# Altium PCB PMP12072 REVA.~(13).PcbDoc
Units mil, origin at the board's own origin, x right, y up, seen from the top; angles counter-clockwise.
Board outline 2500 x 1000 mil, 2 copper layers (Top Layer, Bottom Layer), stack 62 mil thick; 24 components, 17 nets, 101 pads, 28 vias.
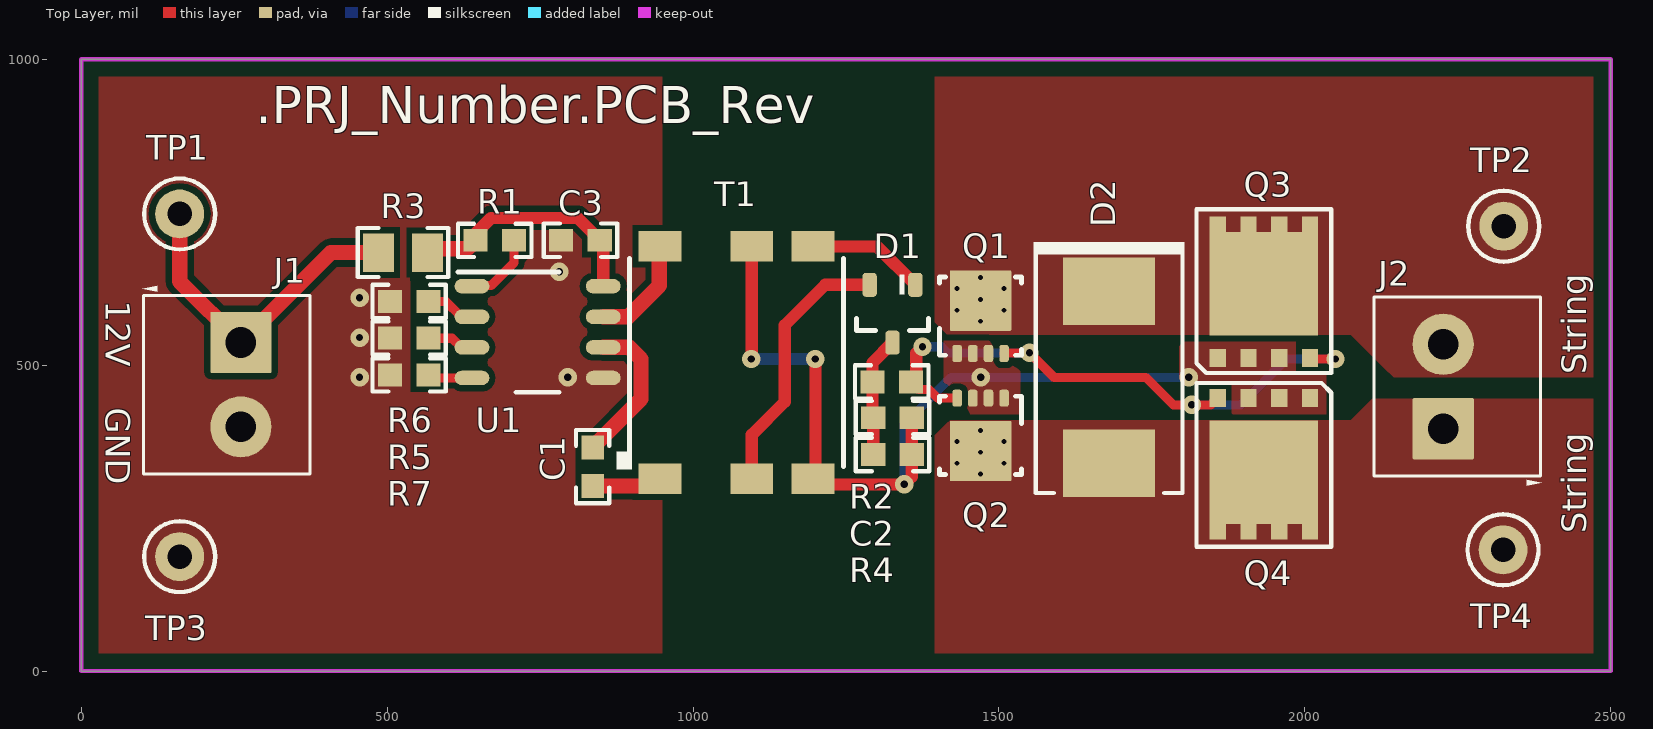
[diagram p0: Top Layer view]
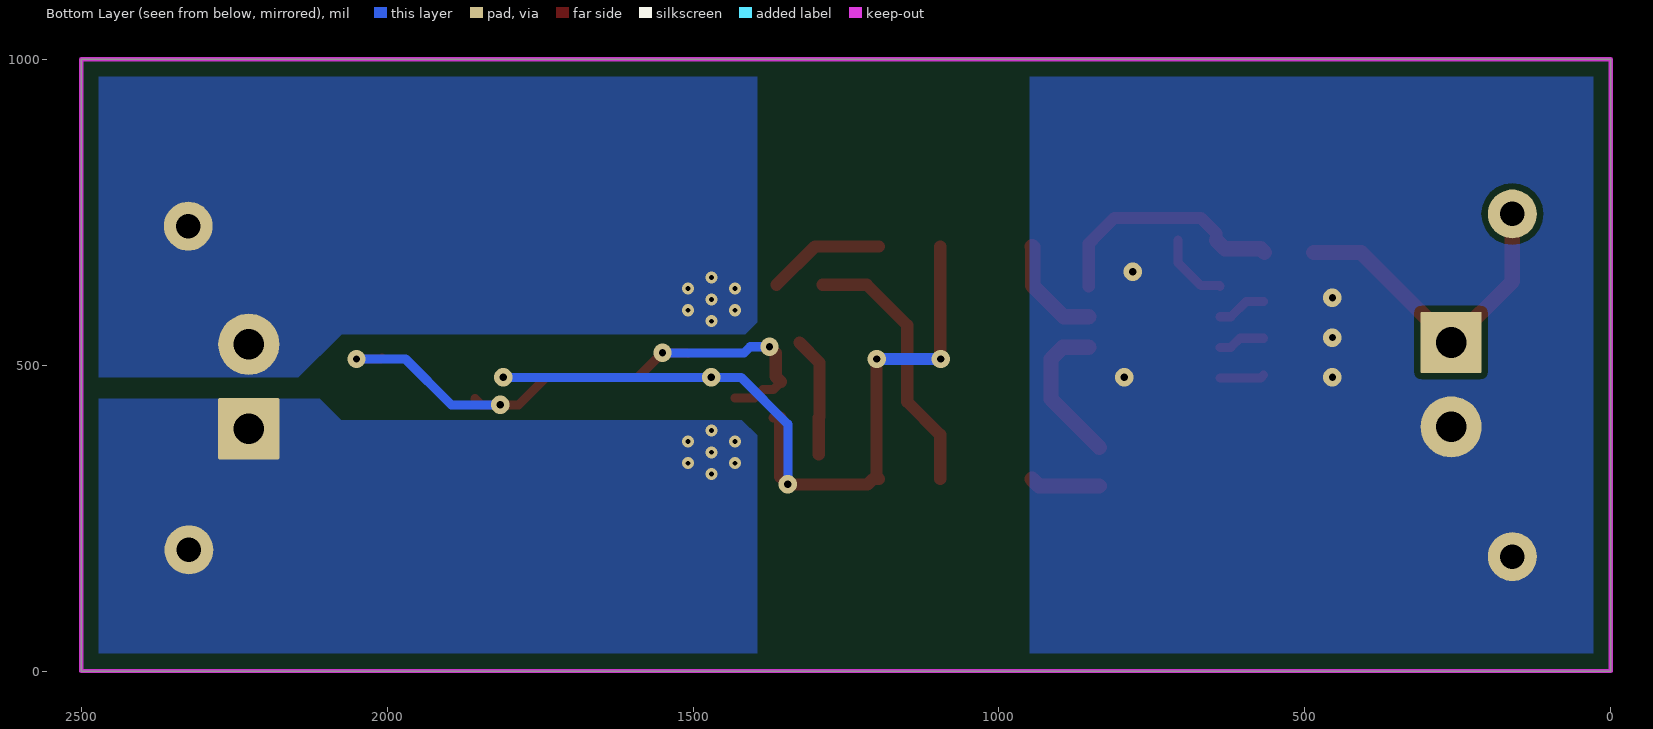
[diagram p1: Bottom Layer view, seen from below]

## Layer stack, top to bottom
Top Solder: solder mask 0.4, Solder Resist, Dk 3.5
Top Layer: signal copper 1.4
Dielectric1: core 59.2, FR-4, Dk 4.8
Bottom Layer: signal copper 1.4
Bottom Solder: solder mask 0.4, Solder Resist, Dk 3.5

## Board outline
0,0 2500,0 2500,1000 0,1000

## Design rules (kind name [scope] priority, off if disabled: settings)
AcuteAngle [All] p1: minimum=4.50000000000000E+0001 checktracksonly=FALSE
AssemblyTestPointUsage [All] p1: valid=2
Clearance Clearance_Keepouts [((IsTrack Or IsArc) And Not InPoly) And IsFree and IsKeepOut vs ((IsTrack Or IsArc) And Not InPoly) And IsFree and IsKeepOut] p1: gap=0
Clearance Clearance_BoardEdge_MountingHoles [OnCopper and InComponentClass('Mounting Holes') vs IsKeepOut] p2: gap=20
Clearance Clearance_BoardEdge_Poly [OnCopper and InPoly vs IsKeepOut] p3: gap=25
Clearance Clearance_BoardEdge [OnCopper and Not InComponentClass('Logo') and not InComponentClass('FiducialMark') and not InRegion(1000,500,4000,800) and Not IsKeepout vs IsKeepOut] p4: gap=25
Clearance Clearance_Poly [InPolygon] p5: gap=10
Clearance [All] p6: gap=7.87
ComponentClearance ComponentClearance_MountingHoles_FiducialMarks [InComponentClass('Mounting Holes') vs InComponentClass('FiducialMark')] p1: gap=50 collisioncheckmode=3 verticalgap=10 showdistances=FALSE
ComponentClearance ComponentClearance_Shunt [InComponentClass('Header') vs InComponentClass('Shunt')] p2: gap=0 collisioncheckmode=3 verticalgap=0 showdistances=FALSE
ComponentClearance ComponentClearance_Logo [InComponentClass('Logo')] p3: gap=50 collisioncheckmode=3 verticalgap=10 showdistances=FALSE
ComponentClearance ComponentClearance_ScrewToNut [(HasFootprint('NY PMS 440 0025 PH')) vs (HasFootprint('Keystone_1902C'))] p4: gap=5 collisioncheckmode=3 verticalgap=10 showdistances=FALSE
ComponentClearance ComponentClearance_MountingHoles [InComponentClass('Mounting Holes')] p5: gap=250 collisioncheckmode=3 verticalgap=100000 showdistances=FALSE
ComponentClearance ComponentClearance_SmallPassives [HasFootprint('0201*') or HasFootprint('0402*') or HasFootprint('0508') or HasFootprint('0603*') or HasFootprint('0612') or HasFootprint('0805*') or HasFootprint('0815*') or HasFootprint('0830*') or HasFootprint('1206*') or HasFootprint('1210*') or HasFootprint('1808*') or HasFootprint('1812*') or HasFootprint('1825*') or HasFootprint('2010*') or HasFootprint('2220*') or HasFootprint('2225*') or HasFootprint('2512*') or HasFootprint('2728*') or HasFootprint('3518*') vs HasFootprint('0201*') or HasFootprint('0402*') or HasFootprint('0508') or HasFootprint('0603*') or HasFootprint('0612') or HasFootprint('0805*') or HasFootprint('0815*') or HasFootprint('0830*') or HasFootprint('1206*') or HasFootprint('1210*') or HasFootprint('1808*') or HasFootprint('1812*') or HasFootprint('1825*') or HasFootprint('2010*') or HasFootprint('2220*') or HasFootprint('2225*') or HasFootprint('2512*') or HasFootprint('2728*') or HasFootprint('3518*')] p6: gap=15 collisioncheckmode=3 verticalgap=10 showdistances=FALSE
ComponentClearance ComponentClearance_THtoSMT [IsThruComponent vs IsSMTComponent] p7: gap=50 collisioncheckmode=3 verticalgap=30 showdistances=FALSE
ComponentClearance ComponentClearance_THtoTH [IsThruComponent vs IsThruComponent] p8: gap=50 collisioncheckmode=3 verticalgap=30 showdistances=FALSE
ComponentClearance [All] p9: gap=20 collisioncheckmode=3 verticalgap=10 showdistances=FALSE
DiffPairsRouting [All] p1: maxlimit=100 minlimit=10 mostfreqgap=10 toplayer_minwidth=15 toplayer_maxwidth=15 toplayer_prefwidth=15 bottomlayer_minwidth=15 bottomlayer_maxwidth=15 bottomlayer_prefwidth=15 maxuncoupledlength=1000
FabricationTestPointUsage TestPointUsage [All] p1: valid=2 allowmultiple=FALSE
FabricationTestpoint Testpoint [All] p1: side=3 testpointundercomponent=TRUE minsize=40 maxsize=100 preferedsize=60 minholesize=0 maxholesize=40 preferedholesize=32 testpointgrid=1 allowsidetop=TRUE allowsidebottom=TRUE usegrid=TRUE gridtolerance=0.01
FanoutControl Fanout_LCC [IsLCC] p1: bgadir=Out bgaviamode=Centered fanoutstyle=Auto fanoutdirection=Alternating viagrid=1 // Fanout_LCC (Default Rule)
FanoutControl Fanout_BGA [IsBGA] p2: bgadir=Out bgaviamode=Centered fanoutstyle=Auto fanoutdirection=Alternating viagrid=1 // Fanout_BGA (Default Rule)
FanoutControl Fanout_Default [All] p4: bgadir=Out bgaviamode=Centered fanoutstyle=Auto fanoutdirection=Alternating viagrid=1 // Fanout_Default (Default Rule)
FanoutControl Fanout_Small [(CompPinCount < 5)] p5: bgadir=Out bgaviamode=Centered fanoutstyle=Auto fanoutdirection=OutThenIn viagrid=1 // Fanout_Small (Default Rule)
HoleSize [All] p1: absolutevalues=TRUE maxlimit=251 minlimit=8 maxpercent=80.000 minpercent=20.000
MinimumAnnularRing MinimumAnnularRing_ThermalPadVias [IsVia and InAnyComponent] p1: minimumring=5.91
MinimumAnnularRing [All] p2: minimumring=9
MinimumSolderMaskSliver MinimumSolderMaskSliver_Logo [InComponentClass('Logo') vs InComponentClass('Logo')] p1: minsoldermaskwidth=0.7
MinimumSolderMaskSliver [All] p2: minsoldermaskwidth=3.94
PlaneClearance [All] p1: clearance=12
PlaneConnect [All] p1: planeconnectstyle=Direct reliefexpansion=10 reliefentries=4 reliefconductorwidth=10 reliefairgap=10
PolygonConnect [All] p1: connectstyle=Direct reliefconductorwidth=10 reliefentries=4 polygonreliefangle="90 Angle" airgapwidth=10
RoutingVias ThermalPadVias [IsVia and InAnyComponent] p1: holewidth=7.87 width=19.68 viastyle="Through Hole" minholewidth=7.87 minwidth=19.68 maxholewidth=12.99 maxwidth=23.62
RoutingVias [All] p2: holewidth=16 width=34 viastyle="Through Hole" minholewidth=7.87 minwidth=26 maxholewidth=40 maxwidth=65
SilkToBoardRegionClearance [Not ((IsComment or IsDesignator) And (Hide <> 'False')) and not InRegion(1000,500,4000,800)] p1:
SilkToSilkClearance SilkToSilkClearance_Pb-FreeLogo [(HasFootprint('Pb-Free_Overlay_Medium') OR HasFootprint('Pb-Free_Overlay_Small')) vs (HasFootprint('Pb-Free_Overlay_Medium') OR HasFootprint('Pb-Free_Overlay_Small'))] p1: silktosilkclearance=0
SilkToSilkClearance [All] p2: silktosilkclearance=0
SilkToSolderMaskClearance SilkToComonentPadClearance [IsPad and InAnycomponent] p1: minsilkscreentomaskgap=5 clearancetoexposedcopper=TRUE
SilkToSolderMaskClearance "Silk to Solder Mask Opening" [All] p2: minsilkscreentomaskgap=0 clearancetoexposedcopper=FALSE
SolderMaskExpansion [All] p1: expansion=1.97
UnpouredPolygon [All] p1: allowunpoured=FALSE
Width [All] p1: maxlimit=100 minlimit=6 preferedwidth=10 checkconnectedcopper=TRUE
13 further rules are at their usual default settings.

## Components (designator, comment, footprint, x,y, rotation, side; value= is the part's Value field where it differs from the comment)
C1 "C1608X7R1H104K" 0603 836,334 r270 top
C2 "C1608X7R1H103K" 0603 1326,414 r0 top
C3 "C1608X5R1C105K" 0603 816,704 r0 top
D1 "BAT54C" SOT-23 1326,584 r270 top
D2 "SMCJ48CA" SMC 1680,480 r270 top
J1 "ED555/2DS" TERM_BLK_ED555-2DS 261,537 r270 top
J2 "ED555/2DS" TERM_BLK_ED555-2DS 2226,396 r90 top
Q1 "CSD19538Q3A" DNH0008A 1470,580 r90 top
Q2 "CSD19538Q3A" DNH0008A 1470,385 r270 top
Q3 "ALT" TRANS_NexFET_Q5A 1933,621 r90 top
Q4 "ALT" TRANS_NexFET_Q5A 1933,337 r270 top
R1 "CRCW060310K0FKEA" 0603 676,704 r180 top
R2 "CRCW06033R30JNEA" 0603 1324.7,472.7 r180 top
R3 "CRCW0805301RFKEA" 0805_HV 526,684 r0 top
R4 "CRCW0603100KFKEA" 0603 1326,354 r180 top
R5 "CRCW06031K00FKEA" 0603 536,544 r180 top
R6 "CRCW060320K0FKEA" 0603 536,604 r180 top
R7 "CRCW060380K6FKEA" 0603 536,484 r180 top
T1 "PA0173NLT" PULSE_PA0173 1086,504 r90 top
TP1 "5000" Keystone5000 161,747 r0 top
TP2 "5000" Keystone5000 2325,727 r0 top
TP3 "5001" Keystone5001 161,187 r0 top
TP4 "5000" Keystone5000 2323.82,198.12 r0 top
U1 "UCC28086D" D0008A_N 746,554 r0 top

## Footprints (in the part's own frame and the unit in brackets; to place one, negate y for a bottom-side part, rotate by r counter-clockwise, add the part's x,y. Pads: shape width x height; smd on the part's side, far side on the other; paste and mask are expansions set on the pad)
0603 [mm] "0603 from SM-752 data"
  rect 1x0.95 smd: 1(-0.8,0) 2(0.8,0)
  silkscreen extent -1.52,-0.69 1.52,0.69, body extent -0.87,-0.47 0.87,0.47, height 1
0805_HV [mil] "0805 with 30mil clearance between pads"
  rect 50x63 smd: 1(-40,0) 2(40,0)
  silkscreen extent -74,-40 74,40, body extent -43,-29 43,29, height 57
D0008A_N [mm] "SOIC, 8-Leads, Body 4.9x3.9mm, Pitch 1.27mm, IPC Medium Density"
  oval 1.45x0.6 smd: 1(-2.725,1.905) 2(-2.725,0.635) 3(-2.725,-0.635) 4(-2.725,-1.905) 5(2.725,-1.905) 6(2.725,-0.635) 7(2.725,0.635) 8(2.725,1.905)
  silkscreen extent -3.3,-2.5 0.9,2.5, body extent -3,-2.45 3,2.45, height 1.63
DNH0008A [mm] "8 pin VSONP, 0.65 mm pitch"
  rrect50% 0.7x0.4 smd paste-0.05 mask-0.05: 1(-1.55,0.975) 2(-1.55,0.325) 3(-1.55,-0.325) 4(-1.55,-0.975) 5(1.55,-0.975) 6(1.55,-0.325) 7(1.55,0.325) 8(1.55,0.975)
  rrect14% 0.705x1.125 on Top Paste: 9(-0.208,0.662) 9(-0.208,-0.663) 9(0.697,-0.663) 9(0.697,0.662)
  rrect6% 1.775x2.45 on Top Solder: 9(0.327,0)
  rrect4% 2.51x2.55 smd paste-1.5 mask-1.5: 9(0.645,0)
  rect 0.5x0.3 on Top Solder: 9(1.175,-0.975) 9(1.175,-0.325) 9(1.175,0.325) 9(1.175,0.975)
  silkscreen extent -1.62,-1.7 1.62,1.7, body extent -1.65,-1.65 1.65,1.66, height 0.91
Keystone5000 [mil] "For Keystone 500x miniature loop terminals"
  round 80 hole 40: 1(0,0)
  silkscreen extent -58,-58 58,58, body extent -49,-49 49,49, height 182
Keystone5001 [mil] "For Keystone 500x miniature loop terminals"
  round 80 hole 40: 1(0,0)
  silkscreen extent -58,-58 58,58, body extent -49,-49 49,49, height 182
PULSE_PA0173 [mil] "PULSE"
  rect 50x70 smd: 1(-190,140) 2(-190,-10) 3(-190,-110) 4(190,-110) 5(190,-10) 6(190,140)
  silkscreen extent -175,-160 170,211, body extent -235,-160 235,190, height 160
SMC [mil] "Molded Diode, 2-Leads, Body 6.9x5.8mm, IPC Medium Density, based on OnSemi component dimensions and land patterns"
  rect 110x150 smd: 1(-140.49,0) 2(140.49,0)
  silkscreen extent -221,-124 189,123, body extent -156,-116 156,116, height 91
SOT-23 [mm] "SOT23, 3-Leads, Body 2.9x1.3mm, Pitch 0.95mm, Lead Span 2.5mm, IPC Medium Density"
  rrect50% 1x0.6 smd: 1(-1.2,0.95) 2(-1.2,-0.95) 3(1.2,0)
  silkscreen extent -1.63,-1.5 0.7,1.5, body extent -1.16,-1.45 1.21,1.45, height 1
TERM_BLK_ED555-2DS [mil]
  rrect4% 100x100 hole 50: 1(0,0)
  round 100 hole 50: 2(138,0)
  silkscreen extent -93,-161 215,113, body extent -69,-150 207,106, height 323
TRANS_NexFET_Q5A [mm] "TI recommended land pattern (nominal) M0139-01"
  rect 0.75x0.675 smd paste-0.1 mask+0.051: 1(-2.776,1.917) 2(-2.776,0.639) 3(-2.776,-0.639) 4(-2.776,-1.917)
  rect 0.655x0.675 smd paste-0.1 mask+0.051: 5(2.776,-1.917) 6(2.776,-0.639) 7(2.776,0.639) 8(2.776,1.917)
  rect 4.295x4.51 smd paste-2.2 mask+0.051: 9(0.301,0)
  silkscreen extent -3.4,-2.8 3.4,2.8, body extent -3.05,-2.5 3.05,2.5, height 1.11

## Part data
C1: "CAP, CERM, 0.1uF, 50V, +/-10%, X7R, 0603"
C2: "CAP, CERM, 0.01uF, 50V, +/-10%, X7R, 0603"
C3: "CAP, CERM, 1uF, 16V, +/-10%, X5R, 0603"
D1: library part BAT54C-7-F, "Diode, Schottky, 30V, 0.2A, SOT-23"
D2: library part SMCJ33CA, "Diode, TVS, Bi, 48V, 1500W, SMC"
J1 J2: "Terminal Block, 6A, 3.5mm Pitch, 2-Pos, TH"
Q1 Q2: "MOSFET, N-CH, 100 V, 5 A, DNH0008A"
Q3 Q4: library part CSD19534Q5A, "MOSFET, SON 5x6mm"
R1: "RES, 10.0 k, 1%, 0.1 W, 0603"
R2: "RES, 3.3 ohm, 5%, 0.1W, 0603"
R3: "RES, 301 ohm, 1%, 0.125W, 0805"
R4: "RES, 100k ohm, 1%, 0.1W, 0603"
R5: "RES, 1.00 k, 1%, 0.1 W, 0603"
R6: "RES, 20.0 k, 1%, 0.1 W, 0603"
R7: "RES, 80.6 k, 1%, 0.1 W, 0603"
T1: "Transformer, Gate Drive, 980uH, SMT"
TP1 TP2 TP4: "Test Point, Miniature, Red, TH"
TP3: "Test Point, Miniature, Black, TH"
U1: "Push-Pull PWM Controller with Programmable Slope Compensation with Current Control, 50 % Duty Cycle, -40 to +85 degC, 8-pin SOIC (D), Green (RoHS & no Sb/Br)"

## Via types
v1: diameter 19.68, hole 7.87, Top Layer to Bottom Layer, 14 vias
v2: diameter 30, hole 12, Top Layer to Bottom Layer, 14 vias

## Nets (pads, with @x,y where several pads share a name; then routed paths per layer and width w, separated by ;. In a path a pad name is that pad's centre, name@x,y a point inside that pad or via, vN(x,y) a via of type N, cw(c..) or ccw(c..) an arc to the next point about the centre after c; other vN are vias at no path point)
GND: C3.1 J1.2 R5.2 R6.2 R7.2 TP3.1 U1.5
  other v2: 455,480 795,480 455,545 455,610 781.43,652.43
NetC1_1: C1.1 U1.6 | length 246.8
  Top Layer w25: C1.1 915,444.5 915,510 896,529 U1.6
NetC1_2: C1.2 T1.1 | length 114.8
  Top Layer w25: C1.2 934.5,302.5 T1.1
NetC2_1: C2.1 D1.3 R2.2 R4.2 | length 196.9
  Top Layer w20: R4.2 C2.1 1293.2,415.3 R2.2 1293.2,503.96 D1.3
NetC2_2: C2.2 Q1.1 Q1.2 Q1.3 Q2.1 Q2.2 Q2.3 Q3.1 Q3.2 Q3.3 Q4.1 Q4.2 Q4.3 R4.1 T1.3 T1.5 | length 1360.5
  Top Layer w15: C2.2 C2.2@1369,414
  Top Layer w20: v2(1095,510) 1096,511 T1.5 ; v2(1200,510) 1200,318 T1.3 1206,314 1215,305 v2(1345,305) 1357.5,317.5 R4.1 C2.2
  Bottom Layer w15: v2(1345,305) 1345,403.43 1421.57,480 v2(1470,480) v2(1809.92,480)
  Bottom Layer w20: v2(1095,510) v2(1200,510)
NetC3_2: C3.2 R1.2 R3.2 U1.8 | length 404.4
  Top Layer w15: C3.2 C3.2@853.28,698.21
  Top Layer w20: R1.2 644.5,715.18 669.9,740.57 811.59,740.57 847.5,704.67 C3.2 ; U1.8 C3.2@853.28,698.21
  Top Layer w25: R3.2 572,690 630.5,690 R1.2
NetD1_1: D1.1 T1.4 | length 193.4
  Top Layer w20: T1.4 1300.65,694 D1.1
NetD1_2: D1.2 T1.2 | length 439.4
  Top Layer w20: T1.2 1096,386 1150,440 1150,565 1216.24,631.24 D1.2
NetD2_1: D2.1 J2.2 Q1.5 Q1.6 Q1.7 Q1.8 Q1.9@1470,605.39 Q3.5 Q3.6 Q3.7 Q3.8 Q3.9 TP2.1
  other v1: 1470,571.83 1431.61,589.65 1508.39,589.65 1470,607.46 1431.61,625.28 1508.39,625.28 1470,643.09
NetD2_2: D2.2 J2.1 Q2.5 Q2.6 Q2.7 Q2.8 Q2.9@1470,359.61 Q4.5 Q4.6 Q4.7 Q4.8 Q4.9 TP4.1
  other v1: 1470,321.91 1431.61,339.72 1508.39,339.72 1470,357.54 1431.61,375.35 1508.39,375.35 1470,393.17
NetJ1_1: J1.1 R3.1 TP1.1 | length 537.3
  Top Layer w25: TP1.1 161,637 J1.1 408,684 R3.1
NetQ1_4: Q1.4 Q2.4 Q3.4 Q4.4 R2.1 | length 1026.6
  Top Layer w15: R2.1 1368.9,460 1385.72,460 1399.7,446.02 Q2.4 ; Q1.4 1509.41,520 v2(1550,520) 1590,480 1740,480 1785,435 v2(1815,435) 1846.2,435 Q4.4@1856.2,445 ; Q3.4 2010.19,510 v2(2050,510)
  Top Layer w20: R2.1 1365,481.5 1365,520 v2(1375,530)
  Bottom Layer w15: v2(1375,530) 1406.45,530 1416.45,520 v2(1550,520) ; v2(1815,435) 1895,435 1970,510 v2(2050,510)
NetR1_1: R1.1 U1.1 | length 121.2
  Top Layer w15: U1.1 639.72,630 670,630 707.5,667.5 R1.1
NetR5_1: R5.1 U1.3 | length 77.4
  Top Layer w15: R5.1 606,544 621,529 U1.3
NetR6_1: R6.1 U1.2 | length 81.6
  Top Layer w15: R6.1 596,604 621,579 U1.2
NetR7_1: R7.1 U1.4 | length 73.3
  Top Layer w15: R7.1 572.5,479 U1.4
NetT1_6: T1.6 U1.7 | length 177.3
  Top Layer w25: U1.7 894,579 945,630 945,693 T1.6
pads on no net: Q1.9@1431.61,626.26 Q1.9@1443.92,571.83 Q1.9@1443.92,607.46 Q1.9@1457.2,626.26 Q1.9@1470,592.89 Q1.9@1482.8,626.26 Q1.9@1496.08,571.83 Q1.9@1496.08,607.46 Q1.9@1508.39,626.26 Q2.9@1431.61,338.74 Q2.9@1443.92,357.54 Q2.9@1443.92,393.17 Q2.9@1457.2,338.74 Q2.9@1470,372.11 Q2.9@1482.8,338.74 Q2.9@1496.08,357.54 Q2.9@1496.08,393.17 Q2.9@1508.39,338.74

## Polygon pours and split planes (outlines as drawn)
GND on Top Layer "Top Layer-No Net 4" (solid, remove dead copper, pour order 26): 0,1000 950,1000 950,0 0,0
NetD2_2 on Top Layer "Top Layer-No Net 3" (solid, remove dead copper, pour order 22): 2075,410 1670,410 1420,410 1415,405 1395,385 1395,380 1395,245 1395,0 2500,0 2500,445 2150,445 2110,445
NetD2_1 on Top Layer "Top Layer-No Net 1" (solid, remove dead copper, pour order 20): 2075,550 1415,550 1395,570 1395,740 1395,1000 2500,1000 2500,480 2200,480 2145,480 2130,495
NetC2_2 on Top Layer "Top Layer-No Net 2" (solid, remove dead copper, pour order 18): 1985,538.32 1985,490 1985.2,489.8 1985.2,486.93 2031.78,486.93 2035,483.71 2035,420 1882.34,420 1880.8,421.54 1880.8,471.07 1801.07,471.07 1800,470 1795,475 1795,535 1800,540 1801.68,538.32 1985,538.32
NetC2_2 on Top Layer "Top Layer-No Net" (solid, remove dead copper, pour order 14): 1420,540 1500,540 1500,500 1525,500 1535,490 1535,480 1535,420 1445,420 1445,460 1420,460 1410,470 1410,540
NetD2_2 on Bottom Layer "Bottom Layer-No Net 2" (solid, remove dead copper, pour order 30): 1420,410 1395,385 1395,0 2500,0 2500,445 2110,445 2075,410
NetD2_1 on Bottom Layer "Bottom Layer-No Net 1" (solid, remove dead copper, pour order 28): 2500,480 2145,480 2075,550 2074.8,550.2 1414.8,550.2 1414.7,550.2 1394.9,570 1395,570.1 1395,1000 2500,1000
GND on Bottom Layer "Bottom Layer-No Net" (solid, remove dead copper, pour order 24): 0,0 0,1000 5,995 950,995 950,0

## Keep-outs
Keep-Out Layer:
  the board outline again, w7
  text ".Layer_Name" at 577,-858.49 h60

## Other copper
Top Layer:
  text ".Layer_Name" at 577,-858.49 h60
Bottom Layer:
  text ".Layer_Name" at 577,-858.49 h60

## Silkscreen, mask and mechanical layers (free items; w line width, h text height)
Top Overlay:
  text ".PRJ_Number" at 285,895 h60
  text ".PCB_Rev" at 810,895 h60
  text "12V" at 40,605 h40 r270
  text "String" at 2460,485 h40 r90
  text "GND" at 40,430 h40 r270
  text "String" at 2460,225 h40 r90
  text ".Layer_Name" at 577,-858.49 h60
Bottom Overlay:
  text ".Layer_Name" at 577,-858.49 h60
Top Paste:
  text ".Layer_Name" at 577,-858.49 h60
Bottom Paste:
  text ".Layer_Name" at 577,-858.49 h60
Top Solder:
  text ".Layer_Name" at 577,-858.49 h60
  text ".Layer_Name" at 577,-858.49 h60
Bottom Solder:
  text ".Layer_Name" at 577,-858.49 h60
Drill Guide:
  text ".Layer_Name" at 577,-858.49 h60
M1 Board Outline:
  the board outline again, w7
  text ".Layer_Name" at 577,-858.49 h60
M2 Board Dimensions:
  rectangle: 125,-400 500,-275
  rectangle: 0,-275 125,-150
  lines w7: 0,-275 1000,-275 ; 125,-400 125,-150 ; 250,-400 250,-150 ; 500,-400 500,-150 ; 750,-400 750,-150 ; 0,-400 0,-150 1000,-150 1000,-400 0,-400
  text ".Layer_Name" at 577,-858.49 h60
M3 3D STEP Top:
  text ".Layer_Name" at 577,-858.49 h60
M4 3D STEP Bottom:
  text ".Layer_Name" at 577,-858.49 h60
M5 Assembly Top:
  lines w10: -292,-930.17 6308,-930.17 ; -292,-726.83 6310,-726.83 ; -292,-523.5 -292,-1133.5 3713,-1133.5 6310,-1133.5 6310,-523.5 -291.5,-523.5 -291.5,-1133.5 1284,-1133.5 ; 2173,-1133.5 2173,-523.5 ; 3440,-726.83 3440,-523.5 ; 4280,-726.83 4280,-523.5 ; 4902,-1140 4902,-937.17
  text "COMPONENTS MARKED 'DNP' SHOULD NOT BE POPULATED." at 1153.5,-318.5 h60
  text "ASSEMBLY VARIANT:" at 1153,-434 h60
  text ".VariantName" at 2189,-434 h60
  text "PCB VIEWED FROM TOP SIDE" at -228.5,-655.67 h60
  text "BOARD #:" at 2248,-655.67 h60
  text ".PRJ_Number" at 2793.5,-655.67 h60
  text "REV:" at 3638,-655.67 h60
  text ".PCB_Rev" at 3929.5,-655.67 h60
  text "SVN REV:" at 4476,-655.67 h60
  text ".VersionControl_RevNumber" at 4982,-655.67 h60
  text "TID #:" at 2248,-859 h60
  text ".TID" at 2793.5,-859 h60
  text "PLOT NAME =" at -228.5,-1064.34 h60
  text ".plot_File_Name" at 577,-1064.34 h60
  text "GENERATED    :" at 2250,-1064.34 h60
  text ".Print_Date" at 3119.5,-1064.34 h60
  text ".Print_Time" at 3848.5,-1064.34 h60
  text "TEXAS INSTRUMENTS" at 5113,-1064.34 h60
M6 Assembly Bottom:
  lines w10: -292.5,-727.33 6309.5,-727.33 ; -290.5,-930.67 6309.5,-930.67 ; 1115.5,-1140.5 1115.5,-937.67 ; 1737.5,-727.33 1737.5,-524 ; 2577.5,-727.33 2577.5,-524 ; 3844.5,-1134 3844.5,-524 ; 4733.5,-1134 6309,-1134 6309,-524 -292.5,-524 -292.5,-1134 2304.5,-1134 6309.5,-1134 6309.5,-524
  text "COMPONENTS MARKED 'DNP' SHOULD NOT BE POPULATED." at 6102,-318 h60
  text ".VariantName" at 5058,-434 h60
  text "ASSEMBLY VARIANT:" at 6097,-434 h60
  text ".VersionControl_RevNumber" at 1035.5,-656.17 h60
  text "SVN REV:" at 1541.5,-656.17 h60
  text ".PCB_Rev" at 2088,-656.17 h60
  text "REV:" at 2379.5,-656.17 h60
  text ".PRJ_Number" at 3224,-656.17 h60
  text "BOARD #:" at 3769.5,-656.17 h60
  text "PCB VIEWED FROM BOTTOM SIDE" at 6246,-656.17 h60
  text ".TID" at 3224,-859.5 h60
  text "TID #:" at 3769.5,-859.5 h60
  text "TEXAS INSTRUMENTS" at 904.5,-1064.84 h60
  text ".Print_Time" at 2169,-1064.84 h60
  text ".Print_Date" at 2898,-1064.84 h60
  text "GENERATED    :" at 3767.5,-1064.84 h60
  text ".plot_File_Name" at 5440.5,-1064.84 h60
  text "PLOT NAME =" at 6246,-1064.84 h60
M9 Title Sheet:
  drawing of 57 lines, arcs and shapes, not listed
  text "1" at 739.84,8036.5 h70
  text "2" at 3235.5,8036.5 h70
  text "3" at 5724.84,8036.5 h70
  text "4" at 8231.51,8036.5 h70
  text "5" at 10730.5,8036.5 h70
  text "6" at 13235.5,8036.5 h70
  text "A" at -416.5,6893.5 h70
  text "A" at 14383.5,6893.5 h70
  text "B" at -416.5,4513.5 h70
  text "B" at 14383.5,4513.5 h70
  text "C" at -416.5,2138.5 h70
  text "C" at 14383.5,2138.5 h70
  text "PROJECT TITLE:" at 11343.5,277.5 h45
  text ".PRJ_Title" at 11393.5,144.17 h70
  text "DESIGNED FOR:" at 11343.5,-23.5 h45
  text ".PRJ_Customer" at 11393.5,-163.5 h70
  text "D" at -416.5,-231.5 h70
  text "D" at 14383.5,-231.5 h70
  text "FILE NAME:" at 11343.5,-323.5 h45
  text ".PCB_File_Name_No_Path" at 11393.5,-443.5 h70
  text "Texas Instruments (TI) and/or its licensors do not warrant the accuracy or completeness of this specification" at 6374,-605.34 h45
  text "ENGINEER:" at 11343.5,-613.5 h45
  text "LAYOUT BY:" at 12848.5,-613.5 h45
  text "or any information contained therein. TI and/or its licensors do not warrant that this design will meet" at 6329.01,-718 h45
  text ".PRJ_Engineer" at 11393.5,-768.49 h70
  text ".PCB_Layout" at 12899,-768.49 h70
  text "the specifications, will be suitable for your application or fit for any particular purpose, or will operate in" at 6329.01,-830.67 h45
  text ".Layer_Name" at 577,-858.49 h60
  text "ALTIUM DESIGNER VERSION:" at 12848.5,-923.5 h45
  text "an implementation. TI and/or its licensors do not warrant that the design is production worthy. You should" at 6329.01,-943.33 h45
  text "completely validate and test your design implementation to confirm the system functionality for your application." at 6374,-1056 h45
  text ".print_Scale" at 11393.5,-1056.83 h70
  text ".Application_BuildNumber" at 12899,-1056.83 h70
  text "1" at 739.84,-1263.5 h70
  text "2" at 3235.5,-1263.5 h70
  text "3" at 5724.84,-1263.5 h70
  text "4" at 8231.51,-1263.5 h70
  text "5" at 10730.5,-1263.5 h70
  text "6" at 13235.5,-1263.5 h70
M10 Fab Notes:
  drawing of 173 lines, arcs and shapes, not listed
  text "DESIGN INFORMATION" at 12377.02,6201 h60
  text "MIN. TRACK WIDTH:" at 11732.46,6021 h60
  text "8" at 12828.7,6021 h60
  text "MIL" at 12983.46,6021 h60
  text "MIN. CLEARANCE:" at 11732.46,5889 h60
  text "0.2" at 12768.7,5889 h60
  text "mm" at 12983.46,5889 h60
  text "MIN. VIA PAD SIZE:" at 11732.46,5757 h60
  text "24" at 12798.71,5757 h60
  text "MIL" at 12983.46,5757 h60
  text "0.05mm (2MIL)" at 12427.46,5615.29 h60
  text "MINIMUM ANNULAR RING" at 11403.23,5611 h60
  text "EXTERNAL" at 13135.46,5611 h60
  text "PER" at 11603.23,5493 h60
  text "IPC-D-275 CLASS 2 LEVEL C" at 11823.23,5493 h60
  text "MIL, HOLES" at 13311.46,5380.71 h60
  text "+/-" at 12919,5380 h60
  text "+/-" at 13773,5380 h60
  text "REGISTRATION TOLERANCES:" at 11403.23,5375 h60
  text "METAL" at 12603,5375 h60
  text "5" at 13179.2,5375 h60
  text "3" at 14012.2,5375 h60
  text "MIL" at 14128.46,5375 h60
  text "+/-" at 13773,5262 h60
  text "HOLE SIZE TOLERANCE (UNLESS OTHERWISE SPECIFIED):" at 11403.23,5257 h60
  text "3" at 14012.2,5257 h60
  text "MIL" at 14128.46,5257 h60
  text "MATERIAL:" at 11328.46,5047.54 h60
  text "FR-4 High Tg" at 12314.9,4907.21 h60
  text "FR-408" at 11749.46,4898.64 h60
  text "OTHER" at 13237.46,4898.64 h60
  text "X" at 12160,4895 h60
  text "62 MIL (1.6mm) +/-10%" at 12069.56,4735.92 h60
  text "THICKNESS:" at 11403.23,4731.64 h60
  text "X" at 11941.4,4731.64 h60
  text "OTHER" at 13354.46,4731.64 h60
  text "TOLERANCE:" at 11403.23,4573.64 h60
  text "X" at 12242.53,4573.64 h60
  text "ANSI IPC-6012 TYPE 3 CLASS 2" at 12429.48,4573.64 h60
  text "OTHER +/-" at 12429.46,4417.64 h60
  text "BOW & TWIST:" at 11403.23,4260.64 h60
  text "X" at 12242.53,4260.64 h60
  text "ANSI IPC-6012 TYPE 3 CLASS 2" at 12429.48,4260.64 h60
  text "OTHER +/-" at 12429.46,4102.13 h60
  text "DRILLING:" at 11328.46,3963.64 h60
  text "REFERENCE:" at 11403.23,3846.64 h60
  text "X" at 12051.46,3846.64 h60
  text "AS SHOWN" at 12238.46,3846.64 h60
  text "X" at 12952.46,3846.64 h60
  text "NC_DRILL FILES" at 13089.46,3846.64 h60
  text "PTH MIN COPPER THICKNESS:" at 11403.23,3688.64 h60
  text "X" at 12753.46,3688.64 h60
  text "1MIL" at 12890.46,3688.64 h60
  text "OTHER" at 13387.46,3688.64 h60
  text "BOARD FINISH:" at 11328.46,3529.64 h60
  text "SILKSCREEN:" at 11483.68,3411.64 h60
  text "X" at 12432.46,3411.64 h60
  text "TOP" at 12558.46,3411.64 h60
  text "X" at 12942.46,3411.64 h60
  text "BOTTOM" at 13069.46,3411.64 h60
  text "SILKSCREEN COLOR:" at 11483.68,3244.64 h60
  text "X" at 12431.42,3244.64 h60
  text "WHITE" at 12558.46,3244.64 h60
  text "OTHER" at 13069.46,3244.64 h60
  text "X" at 12562.42,3085.44 h60
  text "GREEN" at 12689.46,3085.44 h60
  text "OTHER" at 13307.46,3085.44 h60
  text "SOLDER RESIST COLOR:" at 11483.68,3074.64 h60
  text "X" at 12562.42,2915.44 h60
  text "MATTE" at 12689.46,2915.44 h60
  text "SEMI-GLOSS" at 13307,2914.8 h60
  text "IMMERSION GOLD (ENIG)" at 12389.46,2726.92 h60
  text "ENEPIG" at 13727,2723.64 h60
  text "SURFACE FINISH:" at 11328.46,2722.64 h60
  text "X" at 12202.51,2722.64 h60
  text "IMM. TIN/SILVER OR EQUIV" at 11658,2565.64 h60
  text "OTHER" at 13089.46,2565.64 h60
  text "ARRAY/PANEL:" at 11328.46,2386.64 h60
  text "CUT AND TRIM PER M1 BOARD OUTLINE" at 12389.46,2382.35 h60
  text "N.C. ROUTE" at 12389.46,2230.64 h60
  text "X" at 13068.46,2230.64 h60
  text "V. SCORE" at 13255.46,2230.64 h60
  text "CERTIFICATION:" at 11328.46,2093.64 h60
  text "MATERIALS AND WORKMANSHIP FOR ALL PCBS" at 12053.46,2093.64 h60
  text "TO MEET OR EXCEED THE REQUIREMENTS OF:" at 12053.46,1995.64 h60
  text "X" at 11679.96,1859.13 h60
  text "ANSI IPC-A-600F CLASS ->" at 11818.96,1859.13 h60
  text "X" at 13458.02,1859.13 h60
  text "2" at 13576.96,1859.14 h60
  text "1" at 13261.96,1857.64 h60
  text "3" at 13930.96,1857.64 h60
  text "X" at 12494.02,1699.64 h60
  text "RoHS" at 12630.96,1699.64 h60
  text "OTHER" at 13275.36,1699.64 h60
  text "PER ORDER" at 13672.42,1699.64 h60
  text "ALL BOARDS MUST MEET OR EXCEED UL94-V0 REQUIREMENTS." at 11356,1534 h60
  text "PCB MUST BEAR THE UL94V-0 UL REGISTERED MATERIAL ID NUMBER" at 11356,1414 h60
  text "ADDITIONAL REQUIREMENTS:" at 11328.46,1240.64 h60
  text "MICROSECTION:" at 11403.23,1125.64 h60
  text "YES" at 12308.96,1125.64 h60
  text "REQUIRED" at 13170.46,969.49 h60
  text "BARE BOARD ELEC. TEST:" at 11403.23,966.64 h60
  text "NONE" at 12708.96,966.64 h60
  text "X" at 13043.46,966.64 h60
  text "PER ORDER" at 13762.46,966.64 h60
  text ".Layer_Name" at 577,-858.49 h60
M11 Gerber Information:
  lines w10: -292,-930.17 6308,-930.17 ; -292,-726.83 6310,-726.83 ; -292,-523.5 -292,-1133.5 3713,-1133.5 6310,-1133.5 6310,-523.5 -291.5,-523.5 -291.5,-1133.5 1284,-1133.5 ; 2173,-1133.5 2173,-523.5 ; 3440,-726.83 3440,-523.5 ; 4280,-726.83 4280,-523.5 ; 4902,-1140 4902,-937.17
  text "ALL ARTWORK VIEWED FROM TOP SIDE" at -228.5,-655.67 h60
  text "BOARD #:" at 2248,-655.67 h60
  text ".PRJ_Number" at 2793.5,-655.67 h60
  text "REV:" at 3638,-655.67 h60
  text ".PCB_Rev" at 3929.5,-655.67 h60
  text "SVN REV:" at 4476,-655.67 h60
  text ".VersionControl_RevNumber" at 4982,-655.67 h60
  text "LAYER NAME =" at -228.5,-858.49 h60
  text "TID #:" at 2248,-859 h60
  text ".TID" at 2793.5,-859 h60
  text "PLOT NAME =" at -228.5,-1064.34 h60
  text ".plot_File_Name" at 577,-1064.34 h60
  text "GENERATED    :" at 2250,-1064.34 h60
  text ".Print_Date" at 3119.5,-1064.34 h60
  text ".Print_Time" at 3848.5,-1064.34 h60
  text "TEXAS INSTRUMENTS" at 5113,-1064.34 h60
M12 Stackup:
  drawing of 191 lines, arcs and shapes, not listed
  text "Layer" at 9790.34,7830 h60
  text "Name" at 10200.26,7830 h60
  text "Material" at 11130,7830 h60
  text "Thickness" at 11989.77,7830 h60
  text "Constant" at 12639.6,7830 h60
  text "Board Layer Stack" at 13209.46,7830 h60
  text "1" at 9790.34,7710 h60
  text "Top Overlay" at 10200.26,7710 h60
  text "2" at 9790.34,7590 h60
  text "Top Solder" at 10200.26,7590 h60
  text "Solder Resist" at 11130,7590 h60
  text "0.40mil" at 11989.77,7590 h60
  text "3.5" at 12639.6,7590 h60
  text "3" at 9790.34,7470 h60
  text "Top Layer" at 10200.26,7470 h60
  text "Copper" at 11130,7470 h60
  text "1.40mil" at 11989.77,7470 h60
  text "4" at 9790.34,7350 h60
  text "Dielectric1" at 10200.26,7350 h60
  text "FR-4" at 11130,7350 h60
  text "59.20mil" at 11989.77,7350 h60
  text "4.8" at 12639.6,7350 h60
  text "5" at 9790.34,7230 h60
  text "Bottom Layer" at 10200.26,7230 h60
  text "Copper" at 11130,7230 h60
  text "1.40mil" at 11989.77,7230 h60
  text "6" at 9790.34,7110 h60
  text "Bottom Solder" at 10200.26,7110 h60
  text "Solder Resist" at 11130,7110 h60
  text "0.40mil" at 11989.77,7110 h60
  text "3.5" at 12639.6,7110 h60
  text "7" at 9790.34,6990 h60
  text "Bottom Overlay" at 10200.26,6990 h60
  text ".Layer_Name" at 577,-858.49 h60
M13 Component Bodies Top:
  text ".Layer_Name" at 577,-858.49 h60
M14 Component Bodies Bottom:
  text ".Layer_Name" at 577,-858.49 h60
M15 Courtyards Top:
  text ".Layer_Name" at 577,-858.49 h60
M16 Courtyards Bottom:
  text ".Layer_Name" at 577,-858.49 h60
Drill Drawing:
  circle w1: c5692.72,3221.04 r24.89
  lines w1: 5667.83,2760.64 5680.27,2760.64 5692.72,2748.2 5705.16,2760.64 5717.6,2760.64 5705.16,2773.08 5717.6,2785.53 5705.16,2785.53 5692.72,2797.97 5680.27,2785.53 5667.83,2785.53 5680.27,2773.08 5667.83,2760.64 ; 5667.83,2947.29 5717.6,2947.29 5692.72,2897.52 5667.83,2947.29 ; 5667.83,3046.84 5667.83,3059.28 5680.27,3071.72 5667.83,3084.17 5667.83,3096.61 5680.27,3096.61 5692.72,3084.17 5705.16,3096.61 5717.6,3096.61 5717.6,3084.17 5705.16,3071.72 5717.6,3059.28 5717.6,3046.84 5705.16,3046.84 5692.72,3059.28 5680.27,3046.84 5667.83,3046.84
  lines w12: 5600,2703.4 7718.02,2703.4 ; 5600,3300.68 7718.02,3300.68 ; 5970.36,2554.08 5970.36,3450 ; 6327.36,2554.08 6327.36,3450 ; 6988.93,2554.08 6988.93,3450 ; 7273.07,2554.08 7273.07,3450 ; 5600,2554.08 7718.02,2554.08 7718.02,3450 5600,3450 5600,2554.08
  text "Symbol" at 5689.59,3345.48 h72
  text "Quantity" at 6015.16,3345.48 h72
  text "Finished Hole Size" at 6372.16,3345.48 h72
  text "Plated" at 7033.72,3345.48 h72
  text "Hole Type" at 7317.86,3345.48 h72
  text "14" at 6015.16,3196.16 h60
  text "7.87mil (0.200mm)" at 6372.16,3196.16 h60
  text "PTH" at 7033.72,3196.16 h60
  text "Round" at 7317.86,3196.16 h60
  text "14" at 6015.16,3046.84 h60
  text "12.00mil (0.305mm)" at 6372.16,3046.84 h60
  text "PTH" at 7033.72,3046.84 h60
  text "Round" at 7317.86,3046.84 h60
  text "4" at 6015.16,2897.52 h60
  text "40.00mil (1.016mm)" at 6372.16,2897.52 h60
  text "PTH" at 7033.72,2897.52 h60
  text "Round" at 7317.86,2897.52 h60
  text "4" at 6015.16,2748.2 h60
  text "50.00mil (1.270mm)" at 6372.16,2748.2 h60
  text "PTH" at 7033.72,2748.2 h60
  text "Round" at 7317.86,2748.2 h60
  text "36 Total" at 6015.16,2598.88 h60
  text ".Layer_Name" at 577,-858.49 h60

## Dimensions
0,0 to 2500,0 on M2 Board Dimensions
0,0 to 0,1000 on M2 Board Dimensions
0,-400 to 1000,-400 on M2 Board Dimensions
